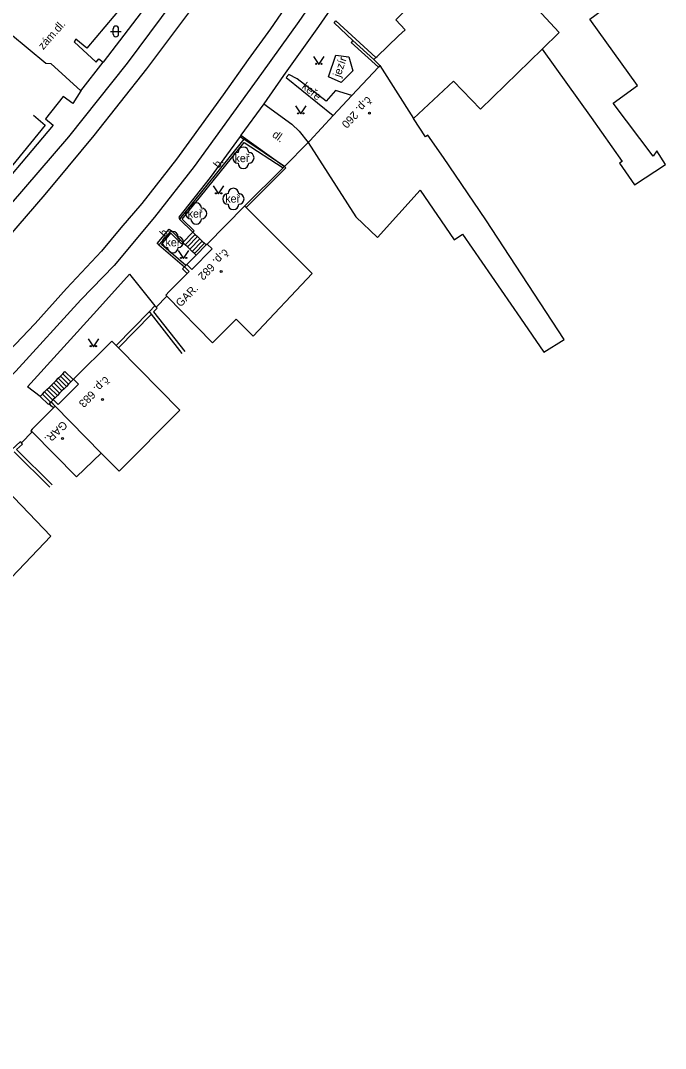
# Model space of a CAD drawing. Extents: x -577457 to -568404, y -1208466 to -1201387.
# Drawn here: x -569092.8 to -569032.3, y -1204665.1 to -1204568.7 of the extents above; entities that cross this region are included whole.
import ezdxf

# ---------------------------------------------------------------- set-up
doc = ezdxf.new("R2010")
doc.units = 0
for name, color, linetype in [('BUDOVY_MĚŘ', 7, 'Continuous'), ('BUDOVY_NEMĚŘ', 7, 'Continuous'), ('OBVOD_PILÍŘE', 7, 'Continuous'), ('POMOC_POPIS', 7, 'Continuous'), ('ROZHRANÍ_PLOCH', 7, 'Continuous'), ('ZELEŇ', 7, 'Continuous'), ('ZN_BUDOV', 7, 'Continuous'), ('ZN_DOPLŇKOVÉ', 7, 'Continuous'), ('ZN_KULTUR', 7, 'Continuous'), ('Č_POPIS_ORIENT', 7, 'Continuous')]:
    doc.layers.add(name, color=color, linetype=linetype)

msp = doc.modelspace()

# ---------------------------------------------------------------- linework, layer by layer
at = {"layer": 'BUDOVY_MĚŘ'}
for points in [[(-569057.34, -1204570.18), (-569056.74, -1204569.61), (-569057.6, -1204568.67), (-569055.94, -1204567.04)], [(-569059.67, -1204572.4), (-569059.48, -1204572.22)], [(-569059.48, -1204572.22), (-569059.35, -1204572.1)], [(-569059.23, -1204573.11), (-569061.72, -1204575.77)], [(-569059.09, -1204572.96), (-569059.67, -1204572.4)], [(-569059.09, -1204572.96), (-569059.23, -1204573.11)], [(-569061.72, -1204575.77), (-569063.47, -1204577.64)], [(-569063.47, -1204577.64), (-569065.67, -1204580.01)], [(-569065.67, -1204580.01), (-569065.81, -1204580.16)], [(-569071.77, -1204586.13), (-569075.29, -1204589.68)], [(-569071.64, -1204586.26), (-569071.77, -1204586.13)], [(-569075.29, -1204589.68), (-569074.83, -1204590.14), (-569076.73, -1204592.06), (-569077.19, -1204591.6)], [(-569075.29, -1204589.68), (-569075.38, -1204589.77)], [(-569075.38, -1204589.77), (-569076.33, -1204590.73)], [(-569077.19, -1204591.6), (-569077.27, -1204591.68)], [(-569076.33, -1204590.73), (-569077.19, -1204591.6)], [(-569077.27, -1204591.68), (-569077.4, -1204591.81)], [(-569077.4, -1204591.81), (-569076.96, -1204592.25)], [(-569077.38, -1204592.67), (-569076.96, -1204592.25)], [(-569079.07, -1204594.58), (-569079.17, -1204594.48), (-569078.83, -1204594.14)], [(-569083.81, -1204599.19), (-569084.23, -1204598.77), (-569087.8, -1204602.35)], [(-569083.59, -1204599.41), (-569083.81, -1204599.19)], [(-569087.8, -1204602.35), (-569087.34, -1204602.81), (-569089.25, -1204604.72), (-569089.71, -1204604.26)], [(-569088.48, -1204603.02), (-569088.69, -1204603.24)], [(-569088.27, -1204602.82), (-569088.48, -1204603.02)], [(-569088.05, -1204602.6), (-569088.27, -1204602.82)], [(-569087.84, -1204602.39), (-569088.05, -1204602.6)], [(-569087.8, -1204602.35), (-569087.84, -1204602.39)], [(-569089.54, -1204604.09), (-569089.71, -1204604.26)], [(-569089.32, -1204603.87), (-569089.54, -1204604.09)], [(-569089.11, -1204603.66), (-569089.32, -1204603.87)], [(-569088.9, -1204603.45), (-569089.11, -1204603.66)], [(-569088.69, -1204603.24), (-569088.9, -1204603.45)], [(-569089.75, -1204604.3), (-569089.92, -1204604.47)], [(-569089.92, -1204604.47), (-569089.52, -1204604.87)], [(-569089.52, -1204604.87), (-569089.89, -1204605.24)], [(-569089.71, -1204604.26), (-569089.75, -1204604.3)], [(-569091.68, -1204607.03), (-569091.81, -1204607.17), (-569091.7, -1204607.28)]]:
    msp.add_lwpolyline(points, dxfattribs=at)
at = {"layer": 'BUDOVY_NEMĚŘ'}
for points in [[(-569043.89, -1204571.42), (-569039.28, -1204577.84), (-569036.4, -1204581.95), (-569036.65, -1204582.12), (-569035.23, -1204584.14), (-569032.33, -1204582.24), (-569033.14, -1204580.95), (-569033.48, -1204581.44), (-569037.23, -1204576.47), (-569034.96, -1204574.82), (-569039.42, -1204568.62), (-569037.89, -1204567.48), (-569040.68, -1204564.59), (-569035.18, -1204559.28)], [(-569050.15, -1204561.38), (-569042.28, -1204569.87), (-569043.89, -1204571.42)], [(-569043.89, -1204571.42), (-569049.66, -1204577.04), (-569052.19, -1204574.42), (-569055.95, -1204577.92)], [(-569059.09, -1204572.96), (-569055.95, -1204577.92)], [(-569065.81, -1204580.16), (-569061.34, -1204587.13), (-569059.31, -1204589.07), (-569055.31, -1204584.64), (-569052.13, -1204589.3), (-569051.34, -1204588.76), (-569045.93, -1204596.63), (-569043.73, -1204599.82), (-569041.82, -1204598.64), (-569049.15, -1204587.41), (-569053.12, -1204581.56), (-569054.61, -1204579.49), (-569054.82, -1204579.63), (-569055.95, -1204577.92)], [(-569071.64, -1204586.26), (-569065.44, -1204592.43), (-569070.96, -1204598.31), (-569072.58, -1204596.72), (-569074.77, -1204598.93), (-569079.07, -1204594.58)], [(-569085.23, -1204609.27), (-569083.52, -1204610.97), (-569077.85, -1204605.24), (-569083.59, -1204599.41)], [(-569085.23, -1204609.27), (-569089.52, -1204604.87)], [(-569091.7, -1204607.28), (-569087.53, -1204611.51), (-569085.23, -1204609.27)], [(-569095.49, -1204611.28), (-569089.93, -1204617.05), (-569095.46, -1204622.83), (-569097.3, -1204621.05)]]:
    msp.add_lwpolyline(points, dxfattribs=at)
at = {"layer": 'OBVOD_PILÍŘE'}
for points in [[(-569077.38, -1204592.23), (-569077.6, -1204592.01), (-569077.4, -1204591.81), (-569076.96, -1204592.25), (-569077.16, -1204592.45), (-569077.38, -1204592.23)], [(-569089.88, -1204604.86), (-569090.06, -1204604.67), (-569089.89, -1204604.5), (-569089.52, -1204604.87), (-569089.69, -1204605.04), (-569089.88, -1204604.86)]]:
    msp.add_lwpolyline(points, dxfattribs=at)
at = {"layer": 'ROZHRANÍ_PLOCH'}
for points in [[(-569193.54, -1204654.14), (-569180.57, -1204647.46), (-569168.09, -1204641.22), (-569155.65, -1204634.81), (-569151.19, -1204632.37), (-569146.32, -1204629.48), (-569140.18, -1204625.55), (-569133.63, -1204621.26), (-569127.76, -1204617.05), (-569123.45, -1204613.78), (-569117.55, -1204608.82), (-569108.26, -1204600.74), (-569100.71, -1204593.46), (-569095.2, -1204587.67), (-569088.24, -1204579.64), (-569082.76, -1204572.74), (-569075.37, -1204562.81), (-569068.38, -1204552.55), (-569060.81, -1204541.45), (-569052.52, -1204528.77), (-569045.02, -1204517.63), (-569041.38, -1204511.96), (-569040.25, -1204510.21)], [(-569065.63, -1204542.48), (-569065.75, -1204542.69), (-569064.6, -1204543.84), (-569070.27, -1204552.24), (-569078.14, -1204545.53), (-569079.98, -1204547.72), (-569071.85, -1204554.55), (-569077.99, -1204563.35), (-569078.76, -1204562.85), (-569080.29, -1204564.84), (-569079.54, -1204565.42), (-569085.02, -1204572.63)], [(-569044.66, -1204554.5), (-569048.15, -1204551.02), (-569048.94, -1204551.78), (-569049.74, -1204550.95), (-569048.98, -1204550.15), (-569050.64, -1204548.37), (-569058.58, -1204560.2), (-569064.84, -1204569.3), (-569068.12, -1204573.89), (-569069.96, -1204576.55)], [(-569060.29, -1204559.54), (-569066.68, -1204568.82), (-569070.19, -1204573.7), (-569076.49, -1204582.43), (-569080.22, -1204587.16), (-569084, -1204591.7), (-569087.11, -1204594.92), (-569093.21, -1204601.6), (-569097.69, -1204606.02), (-569102.1, -1204610.22), (-569107.32, -1204614.75), (-569110.42, -1204617.29), (-569116.08, -1204621.85), (-569125.39, -1204628.71), (-569131.47, -1204632.86), (-569139.26, -1204637.78), (-569143.99, -1204640.64), (-569151.95, -1204644.84), (-569160.44, -1204649.08), (-569170.78, -1204654.41), (-569181.38, -1204659.73), (-569191.89, -1204665.05)], [(-569090.83, -1204559.82), (-569089.58, -1204560.82), (-569092.11, -1204563.73), (-569087.76, -1204567.49), (-569084.78, -1204564.1), (-569082.33, -1204566.3), (-569086.56, -1204571.33), (-569087.6, -1204570.5), (-569087.76, -1204570.73), (-569085.69, -1204572.64), (-569085.43, -1204572.32), (-569085.02, -1204572.63)], [(-569076.01, -1204566.61), (-569079, -1204570.64), (-569080.98, -1204573.27), (-569085.9, -1204579.51), (-569088.34, -1204582.44), (-569090.51, -1204585.03), (-569094.01, -1204589.11)], [(-569068.04, -1204567.6), (-569069.36, -1204569.52), (-569071.43, -1204572.39), (-569073.78, -1204575.7), (-569078.15, -1204581.72), (-569081.42, -1204585.89), (-569083.39, -1204588.17), (-569085.19, -1204590.36), (-569088.47, -1204593.84), (-569091.4, -1204597.12), (-569091.46, -1204597.18), (-569094.39, -1204600.28)], [(-569095.39, -1204568.62), (-569090.4, -1204572.75), (-569089.94, -1204572.78), (-569087.13, -1204575.33)], [(-569062.73, -1204574.54), (-569063.92, -1204574.01), (-569063.22, -1204572), (-569062, -1204572.13), (-569061.64, -1204573.44), (-569062.73, -1204574.54)], [(-569087.13, -1204575.33), (-569085.02, -1204572.63)], [(-569087.13, -1204575.33), (-569087.86, -1204576.53), (-569088.79, -1204575.85), (-569090.44, -1204577.95), (-569089.71, -1204578.56), (-569096.6, -1204586.67), (-569096.95, -1204586.48), (-569100.8, -1204582.9)], [(-569069.96, -1204576.55), (-569072.12, -1204579.49)], [(-569069.96, -1204576.55), (-569067.34, -1204578.44), (-569066.66, -1204579.1), (-569065.81, -1204580.16)], [(-569072.19, -1204579.6), (-569075.01, -1204583.44), (-569077.94, -1204587.17), (-569077.87, -1204587.36)], [(-569072.12, -1204579.49), (-569072.19, -1204579.6)], [(-569072.19, -1204579.6), (-569071.84, -1204579.87)], [(-569072.12, -1204579.49), (-569068.04, -1204582.42)], [(-569079.82, -1204589.76), (-569079.96, -1204589.64), (-569078.84, -1204588.29), (-569078.64, -1204588.44)], [(-569077.56, -1204589.54), (-569076.62, -1204588.57)], [(-569076.62, -1204588.57), (-569076.41, -1204588.78)], [(-569077.34, -1204589.75), (-569077.56, -1204589.54)], [(-569076.41, -1204588.78), (-569077.34, -1204589.75)], [(-569076.19, -1204588.99), (-569077.13, -1204589.96)], [(-569075.97, -1204589.2), (-569076.92, -1204590.17)], [(-569075.76, -1204589.41), (-569076.7, -1204590.38)], [(-569075.54, -1204589.61), (-569076.48, -1204590.58)], [(-569076.41, -1204588.78), (-569076.19, -1204588.99)], [(-569076.19, -1204588.99), (-569075.97, -1204589.2)], [(-569075.97, -1204589.2), (-569075.76, -1204589.41)], [(-569075.76, -1204589.41), (-569075.54, -1204589.61)], [(-569075.54, -1204589.61), (-569075.38, -1204589.77)], [(-569077.13, -1204589.96), (-569077.34, -1204589.75)], [(-569076.92, -1204590.17), (-569077.13, -1204589.96)], [(-569076.7, -1204590.38), (-569076.92, -1204590.17)], [(-569076.48, -1204590.58), (-569076.7, -1204590.38)], [(-569076.33, -1204590.73), (-569076.48, -1204590.58)], [(-569090.94, -1204603.96), (-569092.11, -1204603.06), (-569085.61, -1204595.91), (-569082.57, -1204592.5), (-569080.18, -1204595.48)], [(-569089.24, -1204602.26), (-569089.03, -1204602.05)], [(-569089.03, -1204602.05), (-569088.82, -1204601.83)], [(-569088.27, -1204602.82), (-569089.03, -1204602.05)], [(-569088.82, -1204601.83), (-569088.61, -1204601.62), (-569087.84, -1204602.39)], [(-569088.05, -1204602.6), (-569088.82, -1204601.83)], [(-569090.3, -1204603.32), (-569090.09, -1204603.11)], [(-569090.09, -1204603.11), (-569089.88, -1204602.9)], [(-569089.32, -1204603.87), (-569090.09, -1204603.11)], [(-569089.88, -1204602.9), (-569089.67, -1204602.69)], [(-569089.11, -1204603.66), (-569089.88, -1204602.9)], [(-569089.67, -1204602.69), (-569089.45, -1204602.48)], [(-569088.9, -1204603.45), (-569089.67, -1204602.69)], [(-569089.45, -1204602.48), (-569089.24, -1204602.26)], [(-569088.69, -1204603.24), (-569089.45, -1204602.48)], [(-569088.48, -1204603.02), (-569089.24, -1204602.26)], [(-569090.94, -1204603.96), (-569090.73, -1204603.75)], [(-569089.96, -1204604.51), (-569090.17, -1204604.72), (-569090.94, -1204603.96)], [(-569090.73, -1204603.75), (-569090.52, -1204603.53)], [(-569089.96, -1204604.51), (-569090.73, -1204603.75)], [(-569090.52, -1204603.53), (-569090.3, -1204603.32)], [(-569089.75, -1204604.3), (-569090.52, -1204603.53)], [(-569089.54, -1204604.09), (-569090.3, -1204603.32)], [(-569089.92, -1204604.47), (-569089.96, -1204604.51)]]:
    msp.add_lwpolyline(points, dxfattribs=at)
at = {"layer": 'ZELEŇ'}
msp.add_lwpolyline([(-569061.72, -1204575.77), (-569063.27, -1204575.31), (-569064.13, -1204576.29), (-569066.85, -1204574.22), (-569067.62, -1204573.8), (-569067.87, -1204574.07), (-569063.47, -1204577.64)], dxfattribs=at)
for centre in [(-569071.89, -1204581.6), (-569072.83, -1204585.46), (-569076.32, -1204586.82), (-569078.5, -1204589.51)]:
    msp.add_circle(centre, 0.0005, dxfattribs=at)
for centre, start, end in [((-569071.89, -1204581.1), 0, 179.99999), ((-569072.39, -1204581.6), 89.99999, 269.99999), ((-569071.39, -1204581.6), 270, 89.99999), ((-569071.89, -1204582.1), 179.99999, 359.99999), ((-569072.83, -1204584.96), 0, 179.99999), ((-569076.32, -1204586.32), 0, 179.99999), ((-569073.33, -1204585.46), 89.99999, 269.99999), ((-569072.33, -1204585.46), 270, 89.99999), ((-569076.82, -1204586.82), 89.99999, 269.99999), ((-569075.82, -1204586.82), 270, 89.99999), ((-569072.83, -1204585.96), 179.99999, 359.99999), ((-569076.32, -1204587.32), 179.99999, 359.99999), ((-569078.5, -1204589.01), 0, 179.99999), ((-569079, -1204589.51), 89.99999, 269.99999), ((-569078, -1204589.51), 270, 89.99999), ((-569078.5, -1204590.01), 179.99999, 359.99999)]:
    msp.add_arc(centre, 0.5, start, end, dxfattribs=at)
at = {"layer": 'ZN_BUDOV'}
for centre in [(-569060.08, -1204577.43), (-569073.98, -1204592.25), (-569085.1, -1204604.24), (-569088.85, -1204607.9)]:
    msp.add_circle(centre, 0.0875, dxfattribs=at)
at = {"layer": 'ZN_DOPLŇKOVÉ'}
for points in [[(-569061.64, -1204570.6), (-569063.37, -1204568.95), (-569063.22, -1204568.78), (-569059.48, -1204572.22)], [(-569059.35, -1204572.1), (-569057.34, -1204570.18)], [(-569061.64, -1204570.6), (-569061.8, -1204570.79), (-569059.23, -1204573.11)], [(-569059.67, -1204572.4), (-569061.64, -1204570.6)], [(-569091.57, -1204577.62), (-569090.47, -1204578.54), (-569096.67, -1204586.14)], [(-569071.84, -1204579.87), (-569077.87, -1204587.36)], [(-569068.04, -1204582.42), (-569071.84, -1204579.87)], [(-569076.62, -1204588.57), (-569076.5, -1204588.44), (-569077.63, -1204587.35), (-569071.81, -1204580.17), (-569068.17, -1204582.55)], [(-569065.81, -1204580.16), (-569068.04, -1204582.42)], [(-569068.17, -1204582.55), (-569071.77, -1204586.13)], [(-569068.04, -1204582.42), (-569067.91, -1204582.55), (-569071.64, -1204586.26)], [(-569068.04, -1204582.42), (-569068.17, -1204582.55)], [(-569077.87, -1204587.36), (-569076.62, -1204588.57)], [(-569078.64, -1204588.44), (-569079.82, -1204589.76)], [(-569077.27, -1204591.68), (-569079.57, -1204589.74), (-569078.7, -1204588.67), (-569077.69, -1204589.67), (-569077.56, -1204589.54)], [(-569077.56, -1204589.54), (-569078.64, -1204588.44)], [(-569079.82, -1204589.76), (-569077.4, -1204591.81)], [(-569078.83, -1204594.14), (-569077.38, -1204592.67)], [(-569079.07, -1204594.58), (-569080.07, -1204595.59)], [(-569083.81, -1204599.19), (-569080.7, -1204596.01)], [(-569083.59, -1204599.41), (-569080.51, -1204596.25)], [(-569080.7, -1204596.01), (-569080.18, -1204595.48)], [(-569080.51, -1204596.25), (-569080.7, -1204596.01)], [(-569077.62, -1204599.95), (-569080.51, -1204596.25)], [(-569080.07, -1204595.59), (-569079.97, -1204595.69), (-569080.31, -1204596.03), (-569077.38, -1204599.76)], [(-569080.18, -1204595.48), (-569080.07, -1204595.59)], [(-569091.68, -1204607.03), (-569089.89, -1204605.24)], [(-569091.7, -1204607.28), (-569092.7, -1204608.31)], [(-569092.7, -1204608.31), (-569092.8, -1204608.2), (-569093.58, -1204608.94)], [(-569089.81, -1204612.24), (-569093.16, -1204608.94), (-569092.59, -1204608.42), (-569092.7, -1204608.31)], [(-569093.37, -1204609.15), (-569090.02, -1204612.45)]]:
    msp.add_lwpolyline(points, dxfattribs=at)
at = {"layer": 'ZN_KULTUR'}
for p, q in [((-569084.34, -1204569.76), (-569083.34, -1204569.76)), ((-569084.09, -1204570.01), (-569084.09, -1204569.51)), ((-569083.59, -1204570.01), (-569083.59, -1204569.51))]:
    msp.add_line(p, q, dxfattribs=at)
for points in [[(-569065.32, -1204572.1), (-569064.82, -1204572.85), (-569064.32, -1204572.1)], [(-569067.01, -1204576.74), (-569066.51, -1204577.49), (-569066.01, -1204576.74)], [(-569074.71, -1204584.23), (-569074.21, -1204584.98), (-569073.71, -1204584.23)], [(-569077.99, -1204590.28), (-569077.49, -1204591.03), (-569076.99, -1204590.28)], [(-569086.45, -1204598.55), (-569085.95, -1204599.3), (-569085.45, -1204598.55)]]:
    msp.add_lwpolyline(points, dxfattribs=at)
for centre in [(-569065.07, -1204572.8), (-569064.57, -1204572.8), (-569066.76, -1204577.44), (-569066.26, -1204577.44), (-569074.46, -1204584.93), (-569073.96, -1204584.93), (-569077.74, -1204590.98), (-569077.24, -1204590.98), (-569086.2, -1204599.25), (-569085.7, -1204599.25)]:
    msp.add_circle(centre, 0.05, dxfattribs=at)
for centre, start, end in [((-569083.84, -1204569.51), 0, 179.99999), ((-569083.84, -1204570.01), 179.99999, 359.99999)]:
    msp.add_arc(centre, 0.25, start, end, dxfattribs=at)

# ---------------------------------------------------------------- texts
at = {"layer": 'POMOC_POPIS'}
for s, rotation, p in [('zám.dl.', 48.54998, (-569090.65, -1204571.53)), ('jezír.', 70.79891, (-569062.81, -1204574.1)), ('dl.', 324.1943, (-569069.25, -1204579.58)), ('b.', 51.16335, (-569074.21, -1204582.63)), ('b.', 48.20523, (-569079.27, -1204589.09)), ('GAR.', 45.26, (-569077.78, -1204595.64)), ('GAR.', 223.05998, (-569088.81, -1204606.2))]:
    msp.add_text(s, height=0.75, rotation=rotation, dxfattribs=at).set_placement(p)
at = {"layer": 'ZELEŇ'}
msp.add_text('keře', height=0.75, rotation=320.9454, dxfattribs=at).set_placement((-569066.47, -1204575.04))
for p in [(-569072.72, -1204582.01), (-569073.59, -1204585.8), (-569077.11, -1204587.21), (-569079.19, -1204589.9)]:
    msp.add_text('keř', height=0.75, dxfattribs=at).set_placement(p)
at = {"layer": 'Č_POPIS_ORIENT'}
for s, rotation, p in [('č.p. 260', 226.97001, (-569060.3, -1204575.79)), ('č.p. 682', 225.24999, (-569073.68, -1204590.08)), ('č.p. 683', 225.04997, (-569084.86, -1204602.02))]:
    msp.add_text(s, height=0.75, rotation=rotation, dxfattribs=at).set_placement(p)

doc.saveas('drawing.dxf')
